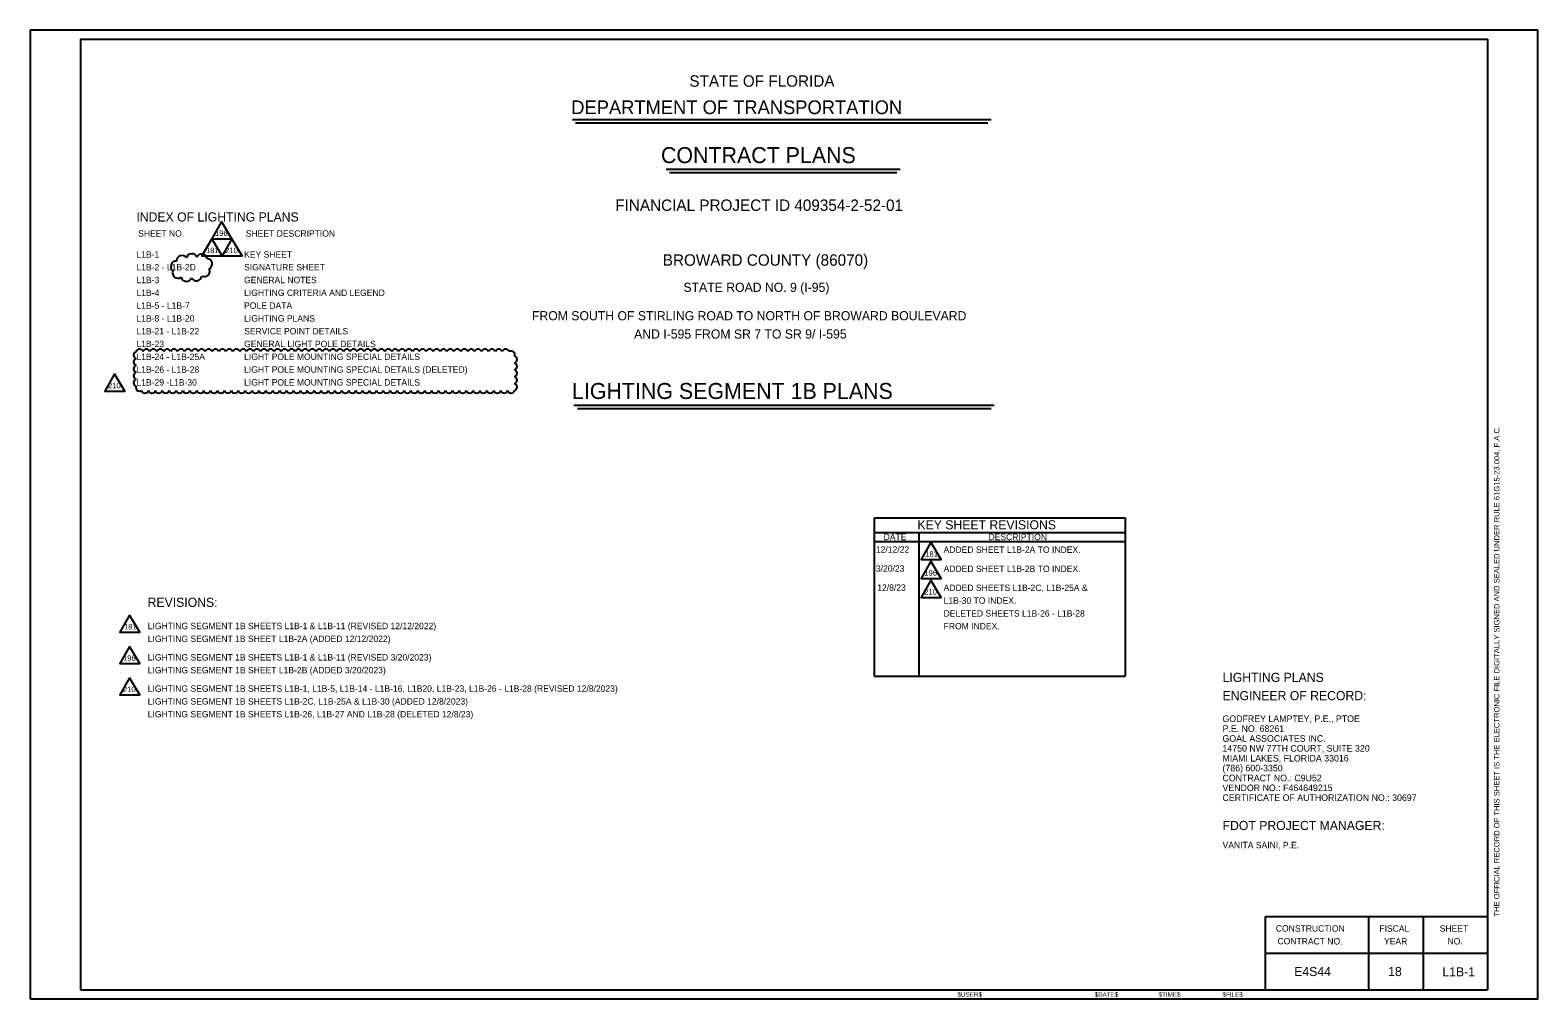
# Model space of a CAD drawing. Extents: x -818.6 to -802.1, y -2197.9 to -2175.
# Drawn here: x -818.56 to -802.06, y -2185.59 to -2174.99 of the extents above; entities that cross this region are included whole.
import ezdxf

# ---------------------------------------------------------------- set-up
doc = ezdxf.new("R2010")
doc.units = 0
for name, color, linetype in [('ActivePointCell_dp', 7, 'Continuous'), ('Cloud_dp', 7, 'Continuous'), ('PlotBorder_dp', 7, 'Continuous'), ('SheetBorder_dp', 7, 'Continuous'), ('SheetLines_dp', 7, 'Continuous'), ('SumBoxLines_dp', 7, 'Continuous'), ('TextLabel', 7, 'Continuous'), ('TextMinor', 7, 'Continuous'), ('TextMisc', 7, 'Continuous'), ('TextNotes', 7, 'Continuous'), ('TextShtNo', 7, 'Continuous'), ('TextTitle', 7, 'Continuous')]:
    doc.layers.add(name, color=color, linetype=linetype)

msp = doc.modelspace()

# ---------------------------------------------------------------- linework, layer by layer
at = {"layer": 'ActivePointCell_dp'}
msp.add_line((-802.614, -2175.094), (-802.614, -2175.094), dxfattribs=at)
at = {"layer": 'Cloud_dp'}
for points in [[(-816.469, -2177.088), (-816.576, -2177.276), (-816.356, -2177.276)], [(-816.576, -2177.276), (-816.684, -2177.464), (-816.463, -2177.464)], [(-816.356, -2177.276), (-816.463, -2177.464), (-816.243, -2177.464)], [(-817.639, -2178.756), (-817.746, -2178.944), (-817.526, -2178.944)], [(-808.706, -2180.597), (-808.814, -2180.785), (-808.593, -2180.785)], [(-808.706, -2180.805), (-808.814, -2180.993), (-808.593, -2180.993)], [(-808.706, -2181.013), (-808.814, -2181.202), (-808.593, -2181.202)], [(-817.475, -2181.394), (-817.583, -2181.582), (-817.362, -2181.582)], [(-817.475, -2181.737), (-817.583, -2181.925), (-817.362, -2181.925)], [(-817.475, -2182.08), (-817.583, -2182.268), (-817.362, -2182.268)]]:
    msp.add_lwpolyline(points, close=True, dxfattribs=at)
for centre, radius, start, end in [((-816.902, -2177.52), 0.06, 35.4166, 180.4166), ((-816.795, -2177.5), 0.0599, 21.2778, 166.2778), ((-816.685, -2177.503), 0.0599, 9.9863, 154.9863), ((-816.632, -2177.553), 0.0599, 298.9542, 83.9542), ((-816.966, -2177.581), 0.0599, 86.9907, 231.9907), ((-816.946, -2177.649), 0.0599, 159.4236, 304.4236), ((-816.657, -2177.632), 0.0599, 241.4449, 26.4449), ((-816.854, -2177.683), 0.0599, 194.4381, 339.4381), ((-816.745, -2177.677), 0.0599, 207.5787, 352.5787), ((-817.366, -2178.524), 0.0396, 17.5, 162.5), ((-817.291, -2178.524), 0.0396, 17.5, 162.5), ((-817.215, -2178.524), 0.0396, 17.5, 162.5), ((-817.139, -2178.524), 0.0396, 17.5, 162.5), ((-817.064, -2178.524), 0.0396, 17.5, 162.5), ((-816.988, -2178.524), 0.0396, 17.5, 162.5), ((-816.913, -2178.524), 0.0396, 17.5, 162.5), ((-816.837, -2178.524), 0.0396, 17.5, 162.5), ((-816.761, -2178.524), 0.0396, 17.5, 162.5), ((-816.686, -2178.524), 0.0396, 17.5, 162.5), ((-816.61, -2178.524), 0.0396, 17.5, 162.5), ((-816.535, -2178.524), 0.0396, 17.5, 162.5), ((-816.459, -2178.524), 0.0396, 17.5, 162.5), ((-816.383, -2178.524), 0.0396, 17.5, 162.5), ((-816.308, -2178.524), 0.0396, 17.5, 162.5), ((-816.232, -2178.524), 0.0396, 17.5, 162.5), ((-816.157, -2178.524), 0.0396, 17.5, 162.5), ((-816.081, -2178.524), 0.0396, 17.5, 162.5), ((-816.005, -2178.524), 0.0396, 17.5, 162.5), ((-815.93, -2178.524), 0.0396, 17.5, 162.5), ((-815.854, -2178.524), 0.0396, 17.5, 162.5), ((-815.779, -2178.524), 0.0396, 17.5, 162.5), ((-815.703, -2178.524), 0.0396, 17.5, 162.5), ((-815.627, -2178.524), 0.0396, 17.5, 162.5), ((-815.552, -2178.524), 0.0396, 17.5, 162.5), ((-815.476, -2178.524), 0.0396, 17.5, 162.5), ((-815.401, -2178.524), 0.0396, 17.5, 162.5), ((-815.325, -2178.524), 0.0396, 17.5, 162.5), ((-815.249, -2178.524), 0.0396, 17.5, 162.5), ((-815.174, -2178.524), 0.0396, 17.5, 162.5), ((-815.098, -2178.524), 0.0396, 17.5, 162.5), ((-815.023, -2178.524), 0.0396, 17.5, 162.5), ((-814.947, -2178.524), 0.0396, 17.5, 162.5), ((-814.871, -2178.524), 0.0396, 17.5, 162.5), ((-814.796, -2178.524), 0.0396, 17.5, 162.5), ((-814.72, -2178.524), 0.0396, 17.5, 162.5), ((-814.645, -2178.524), 0.0396, 17.5, 162.5), ((-814.569, -2178.524), 0.0396, 17.5, 162.5), ((-814.493, -2178.524), 0.0396, 17.5, 162.5), ((-814.418, -2178.524), 0.0396, 17.5, 162.5), ((-814.342, -2178.524), 0.0396, 17.5, 162.5), ((-814.267, -2178.524), 0.0396, 17.5, 162.5), ((-814.191, -2178.524), 0.0396, 17.5, 162.5), ((-814.115, -2178.524), 0.0396, 17.5, 162.5), ((-814.04, -2178.524), 0.0396, 17.5, 162.5), ((-813.964, -2178.524), 0.0396, 17.5, 162.5), ((-813.889, -2178.524), 0.0396, 17.5, 162.5), ((-813.813, -2178.524), 0.0396, 17.5, 162.5), ((-813.737, -2178.524), 0.0396, 17.5, 162.5), ((-813.662, -2178.524), 0.0396, 17.5, 162.5), ((-813.586, -2178.524), 0.0396, 17.5, 162.5), ((-813.511, -2178.524), 0.0396, 17.5, 162.5), ((-813.435, -2178.524), 0.0396, 17.5, 162.5), ((-813.359, -2178.524), 0.0396, 17.5, 162.5), ((-817.392, -2178.55), 0.0396, 107.5, 252.5), ((-817.392, -2178.626), 0.0396, 107.5, 252.5), ((-813.299, -2178.545), 0.0396, 339.0908, 124.0908), ((-813.274, -2178.597), 0.0396, 287.5, 72.5), ((-813.274, -2178.673), 0.0396, 287.5, 72.5), ((-817.392, -2178.701), 0.0396, 107.5, 252.5), ((-817.392, -2178.777), 0.0396, 107.5, 252.5), ((-817.392, -2178.853), 0.0396, 107.5, 252.5), ((-813.274, -2178.748), 0.0396, 287.5, 72.5), ((-813.274, -2178.824), 0.0396, 287.5, 72.5), ((-817.367, -2178.905), 0.0396, 159.0908, 304.0908), ((-817.307, -2178.926), 0.0396, 197.5, 342.5), ((-817.231, -2178.926), 0.0396, 197.5, 342.5), ((-817.156, -2178.926), 0.0396, 197.5, 342.5), ((-817.08, -2178.926), 0.0396, 197.5, 342.5), ((-817.005, -2178.926), 0.0396, 197.5, 342.5), ((-816.929, -2178.926), 0.0396, 197.5, 342.5), ((-816.853, -2178.926), 0.0396, 197.5, 342.5), ((-816.778, -2178.926), 0.0396, 197.5, 342.5), ((-816.702, -2178.926), 0.0396, 197.5, 342.5), ((-816.627, -2178.926), 0.0396, 197.5, 342.5), ((-816.551, -2178.926), 0.0396, 197.5, 342.5), ((-816.475, -2178.926), 0.0396, 197.5, 342.5), ((-816.4, -2178.926), 0.0396, 197.5, 342.5), ((-816.324, -2178.926), 0.0396, 197.5, 342.5), ((-816.249, -2178.926), 0.0396, 197.5, 342.5), ((-816.173, -2178.926), 0.0396, 197.5, 342.5), ((-816.097, -2178.926), 0.0396, 197.5, 342.5), ((-816.022, -2178.926), 0.0396, 197.5, 342.5), ((-815.946, -2178.926), 0.0396, 197.5, 342.5), ((-815.871, -2178.926), 0.0396, 197.5, 342.5), ((-815.795, -2178.926), 0.0396, 197.5, 342.5), ((-815.719, -2178.926), 0.0396, 197.5, 342.5), ((-815.644, -2178.926), 0.0396, 197.5, 342.5), ((-815.568, -2178.926), 0.0396, 197.5, 342.5), ((-815.493, -2178.926), 0.0396, 197.5, 342.5), ((-815.417, -2178.926), 0.0396, 197.5, 342.5), ((-815.341, -2178.926), 0.0396, 197.5, 342.5), ((-815.266, -2178.926), 0.0396, 197.5, 342.5), ((-815.19, -2178.926), 0.0396, 197.5, 342.5), ((-815.115, -2178.926), 0.0396, 197.5, 342.5), ((-815.039, -2178.926), 0.0396, 197.5, 342.5), ((-814.963, -2178.926), 0.0396, 197.5, 342.5), ((-814.888, -2178.926), 0.0396, 197.5, 342.5), ((-814.812, -2178.926), 0.0396, 197.5, 342.5), ((-814.737, -2178.926), 0.0396, 197.5, 342.5), ((-814.661, -2178.926), 0.0396, 197.5, 342.5), ((-814.585, -2178.926), 0.0396, 197.5, 342.5), ((-814.51, -2178.926), 0.0396, 197.5, 342.5), ((-814.434, -2178.926), 0.0396, 197.5, 342.5), ((-814.359, -2178.926), 0.0396, 197.5, 342.5), ((-814.283, -2178.926), 0.0396, 197.5, 342.5), ((-814.207, -2178.926), 0.0396, 197.5, 342.5), ((-814.132, -2178.926), 0.0396, 197.5, 342.5), ((-814.056, -2178.926), 0.0396, 197.5, 342.5), ((-813.981, -2178.926), 0.0396, 197.5, 342.5), ((-813.905, -2178.926), 0.0396, 197.5, 342.5), ((-813.829, -2178.926), 0.0396, 197.5, 342.5), ((-813.754, -2178.926), 0.0396, 197.5, 342.5), ((-813.678, -2178.926), 0.0396, 197.5, 342.5), ((-813.603, -2178.926), 0.0396, 197.5, 342.5), ((-813.527, -2178.926), 0.0396, 197.5, 342.5), ((-813.451, -2178.926), 0.0396, 197.5, 342.5), ((-813.376, -2178.926), 0.0396, 197.5, 342.5), ((-813.3, -2178.926), 0.0396, 197.5, 342.5), ((-813.274, -2178.9), 0.0396, 287.5, 72.5)]:
    msp.add_arc(centre, radius, start, end, dxfattribs=at)
at = {"layer": 'PlotBorder_dp'}
msp.add_lwpolyline([(-818.564, -2185.594), (-802.064, -2185.594), (-802.064, -2174.994), (-818.564, -2174.994)], close=True, dxfattribs=at)
at = {"layer": 'SheetBorder_dp'}
for p, q in [((-818.014, -2175.094), (-818.014, -2185.494)), ((-818.014, -2175.094), (-802.614, -2175.094)), ((-802.614, -2175.094), (-802.614, -2185.494)), ((-818.014, -2185.494), (-802.614, -2185.494))]:
    msp.add_line(p, q, dxfattribs=at)
at = {"layer": 'SheetLines_dp'}
for p, q in [((-805.044, -2184.694), (-802.614, -2184.694)), ((-805.044, -2185.494), (-805.044, -2184.694)), ((-803.914, -2185.494), (-803.914, -2184.694)), ((-803.314, -2185.494), (-803.314, -2184.694)), ((-805.044, -2185.094), (-802.614, -2185.094))]:
    msp.add_line(p, q, dxfattribs=at)
at = {"layer": 'SumBoxLines_dp'}
for p, q in [((-809.327, -2180.33), (-809.327, -2182.063)), ((-809.327, -2180.33), (-806.58, -2180.33)), ((-806.58, -2180.33), (-806.58, -2182.063)), ((-809.327, -2180.49), (-806.58, -2180.49)), ((-809.327, -2180.59), (-806.58, -2180.59)), ((-808.837, -2180.49), (-808.839, -2182.063)), ((-809.327, -2182.063), (-806.58, -2182.063))]:
    msp.add_line(p, q, dxfattribs=at)
at = {"layer": 'TextTitle'}
for p, q in [((-812.63, -2175.97), (-808.048, -2175.97)), ((-812.597, -2176.008), (-808.083, -2176.008)), ((-811.605, -2176.515), (-809.044, -2176.515)), ((-811.566, -2176.553), (-809.077, -2176.553)), ((-812.614, -2179.096), (-808.015, -2179.096)), ((-812.575, -2179.134), (-808.047, -2179.134))]:
    msp.add_line(p, q, dxfattribs=at)

# ---------------------------------------------------------------- texts
at = {"layer": 'Cloud_dp'}
for s, p in [('196', (-816.541, -2177.246)), ('181', (-816.639, -2177.434)), ('210', (-816.429, -2177.434)), ('210', (-817.712, -2178.914)), ('181', (-808.768, -2180.755)), ('196', (-808.778, -2180.963)), ('210', (-808.779, -2181.171)), ('181', (-817.537, -2181.552)), ('196', (-817.547, -2181.895)), ('210', (-817.548, -2182.238))]:
    msp.add_text(s, height=0.06, rotation=0, dxfattribs=at).set_placement(p)
at = {"layer": 'TextLabel'}
for s, height, p in [('FINANCIAL PROJECT ID 409354-2-52-01', 0.125, (-812.16, -2176.972)), ('INDEX OF LIGHTING PLANS', 0.1, (-817.401, -2177.088)), ('L1B-1', 0.07, (-817.4, -2177.483)), ('KEY SHEET', 0.07, (-816.222, -2177.483)), ('BROWARD COUNTY (86070)', 0.125, (-811.64, -2177.572)), ('L1B-2 - L1B-2D', 0.07, (-817.4, -2177.623)), ('SIGNATURE SHEET', 0.07, (-816.222, -2177.623)), ('L1B-3', 0.07, (-817.4, -2177.763)), ('L1B-4', 0.07, (-817.4, -2177.903)), ('GENERAL NOTES', 0.07, (-816.222, -2177.763)), ('LIGHTING CRITERIA AND LEGEND', 0.07, (-816.222, -2177.903)), ('STATE ROAD NO. 9 (I-95)', 0.1, (-811.414, -2177.858)), ('L1B-5 - L1B-7', 0.07, (-817.4, -2178.043)), ('POLE DATA', 0.07, (-816.222, -2178.043)), ('L1B-8 - L1B-20', 0.07, (-817.4, -2178.183)), ('LIGHTING PLANS', 0.07, (-816.222, -2178.183)), ('FROM SOUTH OF STIRLING ROAD TO NORTH OF BROWARD BOULEVARD', 0.1, (-813.072, -2178.169)), ('L1B-21 - L1B-22', 0.07, (-817.4, -2178.323)), ('SERVICE POINT DETAILS', 0.07, (-816.222, -2178.323)), ('AND I-595 FROM SR 7 TO SR 9/ I-595', 0.1, (-811.954, -2178.369)), ('L1B-23', 0.07, (-817.4, -2178.463)), ('GENERAL LIGHT POLE DETAILS', 0.07, (-816.222, -2178.463)), ('L1B-24 - L1B-25A', 0.07, (-817.4, -2178.603)), ('LIGHT POLE MOUNTING SPECIAL DETAILS', 0.07, (-816.222, -2178.603)), ('L1B-26 - L1B-28', 0.07, (-817.4, -2178.743)), ('L1B-29 -L1B-30', 0.07, (-817.4, -2178.883)), ('LIGHT POLE MOUNTING SPECIAL DETAILS (DELETED)', 0.07, (-816.222, -2178.743)), ('LIGHT POLE MOUNTING SPECIAL DETAILS', 0.07, (-816.222, -2178.883)), ('KEY SHEET REVISIONS', 0.1, (-808.853, -2180.457)), ('REVISIONS:', 0.1, (-817.278, -2181.305)), ('LIGHTING PLANS', 0.1, (-805.514, -2182.126)), ('ENGINEER OF RECORD:', 0.1, (-805.514, -2182.326)), ('GODFREY LAMPTEY, P.E., PTOE', 0.07202, (-805.515, -2182.565)), ('P.E. NO. 68261', 0.07202, (-805.515, -2182.673)), ('GOAL ASSOCIATES INC. ', 0.07202, (-805.515, -2182.781)), ('14750 NW 77TH COURT, SUITE 320', 0.07202, (-805.515, -2182.889)), ('MIAMI LAKES, FLORIDA 33016', 0.07202, (-805.515, -2182.997)), ('(786) 600-3350', 0.07202, (-805.515, -2183.105)), ('VENDOR NO.: F464649215', 0.07202, (-805.515, -2183.321)), ('CONTRACT NO.: C9U52', 0.07202, (-805.515, -2183.213)), ('CERTIFICATE OF AUTHORIZATION NO.: 30697', 0.07202, (-805.515, -2183.429)), ('E4S44', 0.1, (-804.73, -2185.345)), ('18', 0.1, (-803.702, -2185.345))]:
    msp.add_text(s, height=height, dxfattribs=at).set_placement(p)
at = {"layer": 'TextMinor'}
for s, height, p in [('12/12/22', 0.07, (-809.308, -2180.712)), ('ADDED SHEET L1B-2A TO INDEX.', 0.07, (-808.567, -2180.714)), ('3/20/23', 0.07, (-809.308, -2180.92)), ('ADDED SHEET L1B-2B TO INDEX.', 0.07, (-808.567, -2180.923)), ('12/8/23', 0.07, (-809.293, -2181.129)), ('ADDED SHEETS L1B-2C, L1B-25A & ', 0.07, (-808.567, -2181.131)), ('L1B-30 TO INDEX.', 0.07, (-808.567, -2181.271)), ('DELETED SHEETS L1B-26 - L1B-28 ', 0.07, (-808.567, -2181.411)), ('FROM INDEX.', 0.07, (-808.567, -2181.551)), ('$USER$', 0.05, (-808.415, -2185.572))]:
    msp.add_text(s, height=height, dxfattribs=at).set_placement(p)
for s, p in [('$DATE$', (-806.915, -2185.572)), ('$TIME$', (-806.215, -2185.572)), ('$FILE$', (-805.515, -2185.572))]:
    msp.add_text(s, height=0.05, rotation=360, dxfattribs=at).set_placement(p)
at = {"layer": 'TextMisc'}
msp.add_text('THE OFFICIAL RECORD OF THIS SHEET IS THE ELECTRONIC FILE DIGITALLY SIGNED AND SEALED UNDER RULE 61G15-23.004, F.A.C.', height=0.06, rotation=90, dxfattribs=at).set_placement((-802.484, -2184.694))
at = {"layer": 'TextNotes'}
for s, height, p in [('SHEET NO.', 0.07, (-817.382, -2177.254)), ('SHEET DESCRIPTION', 0.07, (-816.204, -2177.254)), ('DATE', 0.07, (-809.223, -2180.575)), ('DESCRIPTION', 0.07, (-808.075, -2180.575)), ('LIGHTING SEGMENT 1B SHEETS L1B-1 & L1B-11 (REVISED 12/12/2022)', 0.06998, (-817.277, -2181.549)), ('LIGHTING SEGMENT 1B SHEET L1B-2A (ADDED 12/12/2022)', 0.06998, (-817.277, -2181.689)), ('LIGHTING SEGMENT 1B SHEETS L1B-1 & L1B-11 (REVISED 3/20/2023)', 0.06998, (-817.277, -2181.892)), ('LIGHTING SEGMENT 1B SHEET L1B-2B (ADDED 3/20/2023)', 0.06998, (-817.277, -2182.032)), ('LIGHTING SEGMENT 1B SHEETS L1B-1, L1B-5, L1B-14 - L1B-16, L1B20, L1B-23, L1B-26 - L1B-28 (REVISED 12/8/2023)', 0.069982, (-817.277, -2182.234)), ('LIGHTING SEGMENT 1B SHEETS L1B-2C, L1B-25A & L1B-30 (ADDED 12/8/2023)', 0.06998, (-817.277, -2182.374)), ('LIGHTING SEGMENT 1B SHEETS L1B-26, L1B-27 AND L1B-28 (DELETED 12/8/23)', 0.06998, (-817.277, -2182.514)), ('FDOT PROJECT MANAGER:', 0.1, (-805.514, -2183.747)), ('VANITA SAINI, P.E.', 0.07, (-805.514, -2183.946))]:
    msp.add_text(s, height=height, dxfattribs=at).set_placement(p)
for s, p in [('CONSTRUCTION', (-804.931, -2184.858)), ('CONTRACT NO.', (-804.913, -2184.998)), ('FISCAL', (-803.798, -2184.859)), ('YEAR', (-803.747, -2184.999)), ('SHEET', (-803.138, -2184.859)), ('NO.', (-803.052, -2184.999))]:
    msp.add_text(s, height=0.07, rotation=359.8607, dxfattribs=at).set_placement(p)
at = {"layer": 'TextShtNo'}
msp.add_text('L1B-1', height=0.1, dxfattribs=at).set_placement((-803.108, -2185.348))
at = {"layer": 'TextTitle'}
for s, height, p in [('STATE OF FLORIDA', 0.125, (-811.349, -2175.613)), ('DEPARTMENT OF TRANSPORTATION', 0.15, (-812.642, -2175.913)), ('CONTRACT PLANS', 0.175, (-811.66, -2176.449)), ('LIGHTING SEGMENT 1B PLANS', 0.175, (-812.634, -2179.03))]:
    msp.add_text(s, height=height, dxfattribs=at).set_placement(p)

doc.saveas('drawing.dxf')
